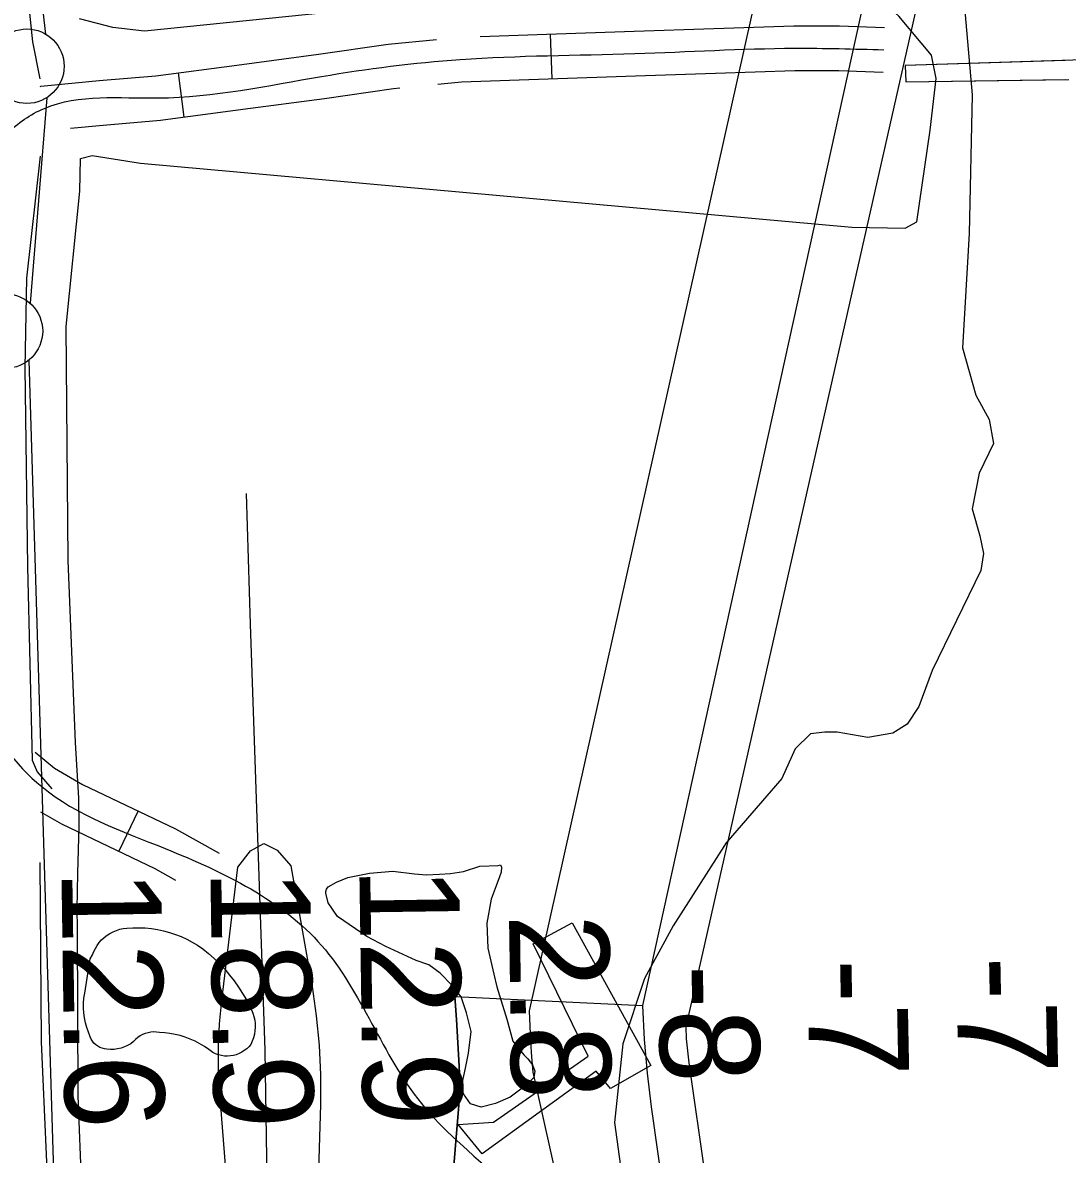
# Model space of a CAD drawing. Extents: x 3651524 to 3689615, y 505651 to 531377.
# Drawn here: x 3657251 to 3657953, y 524242 to 525001 of the extents above; entities that cross this region are included whole.
import ezdxf

# ---------------------------------------------------------------- set-up
doc = ezdxf.new("R2010")
doc.units = 0
for name, color, linetype in [('V-CHAN-DOCK', 7, 'Continuous'), ('V-FLOD-BASE', 7, 'Continuous'), ('V-LEVE-TOET', 7, 'Continuous'), ('V-RIVR-EDGE', 7, 'Continuous'), ('V-RIVR-RANG', 7, 'Continuous'), ('V-ROAD-CNTR', 7, 'Continuous'), ('V-SITE-VEGE', 7, 'Continuous'), ('V-SURV-LINE', 7, 'Continuous'), ('V-TOPO-DPTH', 7, 'Continuous'), ('V-TOPO-MINR', 7, 'Continuous'), ('V-TOPO-SHOR', 7, 'Continuous'), ('V-TOPO-WATR', 7, 'Continuous'), ('V-UTIL-LINE', 7, 'Continuous')]:
    doc.layers.add(name, color=color, linetype=linetype)

msp = doc.modelspace()

# ---------------------------------------------------------------- linework, layer by layer
at = {"layer": 'V-CHAN-DOCK'}
for points in [[(3657963.161, 524976.383), (3657843.67, 524972.508), (3657844.08, 524961.707), (3657953.55, 524963.231)], [(3657951.172, 524975.996), (3657843.67, 524972.508), (3657844.08, 524961.707), (3657951.551, 524963.202)], [(3657543.487, 524261.701), (3657567.221, 524263.255), (3657630.83, 524307.57), (3657593.833, 524382.901), (3657620.162, 524397.055), (3657672.994, 524301.295), (3657645.856, 524285.969), (3657636.183, 524297.598), (3657559.736, 524242.052), (3657543.487, 524261.701)]]:
    msp.add_lwpolyline(points, dxfattribs=at)
at = {"layer": 'V-FLOD-BASE'}
for points in [[(3657233.676, 525796.15), (3657236.817, 525673.28), (3657238.124, 525513.246), (3657239.543, 525359.705), (3657243.953, 525174.816), (3657248.712, 525076.717), (3657257.785, 524988.581), (3657262.659, 524963.696)], [(3657262.921, 524911.732), (3657253.797, 524829.82), (3657252.732, 524769.613), (3657254.508, 524636.141), (3657257.527, 524506.189), (3657260.932, 524498.451), (3657270.767, 524487.058)], [(3657262.808, 524437.601), (3657263.632, 524317.136), (3657270.407, 524165.86), (3657277.304, 524021.671), (3657283.95, 523829.657), (3657284.927, 523784.764)]]:
    msp.add_lwpolyline(points, dxfattribs=at)
at = {"layer": 'V-LEVE-TOET'}
for points in [[(3657290.039, 524910.063), (3657297.915, 524912.164), (3657330.308, 524907.109), (3657807.806, 524863.952), (3657843.636, 524863.317), (3657851.551, 524867.659), (3657860.478, 524929.103), (3657864.451, 524963.755), (3657861.369, 524979.49), (3657839.429, 525005.639), (3657819.592, 525023.909), (3657797.318, 525031.024), (3657765.986, 525032.697), (3657511.399, 525013.675), (3657332.989, 524995.546), (3657311.756, 524998.161), (3657289.334, 525003.955)], [(3657293.346, 524155.741), (3657288.474, 524281.003), (3657288.095, 524393.194), (3657287.735, 524406.191), (3657288.163, 524430.392), (3657289.203, 524461.925), (3657288.947, 524480.824), (3657286.653, 524518.063), (3657281.73, 524640.374), (3657280.372, 524797.457), (3657289.652, 524888.223), (3657290.039, 524910.063)]]:
    msp.add_lwpolyline(points, dxfattribs=at)
at = {"layer": 'V-RIVR-EDGE'}
msp.add_lwpolyline([(3657882.775, 525019.576), (3657888.613, 524952.926), (3657886.582, 524859.88), (3657882.19, 524783.049), (3657891.116, 524751.21), (3657900.081, 524734.979), (3657903.043, 524718.763), (3657893.388, 524698.976), (3657888.526, 524674.975), (3657893.885, 524656.952), (3657896.256, 524644.939), (3657894.427, 524633.537), (3657861.844, 524566.381), (3657852.779, 524542.391), (3657844.945, 524530.404), (3657835.325, 524524.424), (3657818.509, 524521.464), (3657798.107, 524525.116), (3657789.702, 524525.137), (3657780.094, 524523.96), (3657769.863, 524513.78), (3657760.81, 524493.992), (3657723.483, 524450.861), (3657687.926, 524395.118), (3657668.628, 524359.746), (3657654.112, 524315.959), (3657648.578, 524263.143), (3657653.296, 524228.913)], dxfattribs=at)
at = {"layer": 'V-ROAD-CNTR'}
for p, q in [((3657605.412, 524993.672), (3657606.42, 524963.689)), ((3657355.52, 524967.698), (3657359.448, 524937.956)), ((3657328.645, 524472.239), (3657315.762, 524445.146))]:
    msp.add_line(p, q, dxfattribs=at)
for points in [[(3657558.405, 524992.091), (3657603.049, 524993.593), (3657661.682, 524995.563), (3657715.211, 524997.363), (3657768.992, 524999.17), (3657799.559, 524999.21), (3657829.888, 524998.15)], [(3657263.03, 524958.59), (3657263.319, 524958.657), (3657302.595, 524962.439), (3657340.502, 524965.714), (3657395.041, 524972.917), (3657449.814, 524980.093), (3657496.482, 524986.927), (3657528.948, 524990.128)], [(3657530.022, 524960.088), (3657545.902, 524961.654), (3657604.041, 524963.609), (3657662.672, 524965.579), (3657716.221, 524967.379), (3657769.516, 524969.17), (3657799.055, 524969.21), (3657828.84, 524968.168)], [(3657283.312, 524930.443), (3657305.323, 524932.563), (3657343.758, 524935.884), (3657398.953, 524943.173), (3657453.936, 524950.377), (3657500.13, 524957.141), (3657504.385, 524957.561)], [(3657259.698, 524511.607), (3657272.602, 524500.844), (3657291.286, 524490.003), (3657353.843, 524460.257), (3657383.068, 524443.835)], [(3657263.216, 524471.605), (3657277.294, 524463.437), (3657340.037, 524433.603), (3657353.891, 524425.818)]]:
    msp.add_lwpolyline(points, dxfattribs=at)
for points in [[(3657130.748, 524795.433), (3657165.711, 524812.868), (3657188.341, 524836.501), (3657213.423, 524885.57), (3657240.424, 524926.712), (3657265.753, 524943.822), (3657342.13, 524950.799), (3657451.875, 524965.235), (3657544.913, 524976.629), (3657662.177, 524980.571), (3657769.254, 524984.17), (3657829.364, 524983.159)], [(3657129.943, 524655.414), (3657166.389, 524653.332), (3657185.57, 524640.198), (3657200.233, 524605.692), (3657221.299, 524544.671), (3657263.972, 524488.509), (3657346.94, 524446.93), (3657451.918, 524381.84), (3657518.866, 524275.788), (3657590.106, 524205.982), (3657650.646, 524044.599), (3657661.145, 523937.202), (3657682.089, 523855.232), (3657701.882, 523782.87)]]:
    msp.add_spline(points, degree=3, dxfattribs=at)
at = {"layer": 'V-SITE-VEGE'}
msp.add_lwpolyline([(3657570.418, 524435.482), (3657572.044, 524435.992), (3657572.554, 524434.363), (3657572.499, 524431.13), (3657571.362, 524427.914), (3657569.101, 524422.022), (3657565.706, 524412.915), (3657562.724, 524396.789), (3657563.506, 524380.057), (3657567.514, 524362.728), (3657569.519, 524354.063), (3657576.146, 524332.375), (3657580.201, 524317.742), (3657587.586, 524308.444), (3657590.234, 524305.702), (3657593.403, 524301.87), (3657594.945, 524297.528), (3657594.328, 524293.223), (3657588.293, 524287.401), (3657578.456, 524280.024), (3657568.675, 524275.883), (3657558.925, 524273.36), (3657551.953, 524275.639), (3657547.216, 524282.195), (3657546.26, 524289.222), (3657548.599, 524299.429), (3657550.399, 524309.64), (3657552.273, 524324.169), (3657549.256, 524336.627), (3657545.672, 524347.475), (3657539.338, 524355.136), (3657531.393, 524363.367), (3657523.941, 524368.891), (3657515.364, 524371.74), (3657495.037, 524381.267), (3657482.215, 524387.966), (3657474.75, 524392.951), (3657462.497, 524401.255), (3657456.189, 524410.535), (3657454.686, 524417.033), (3657454.704, 524418.11), (3657455.271, 524419.718), (3657456.377, 524421.318), (3657461.827, 524424.457), (3657469.431, 524427.558), (3657484.046, 524430.536), (3657499.709, 524431.877), (3657514.235, 524430.001), (3657522.313, 524429.319), (3657530.949, 524429.706), (3657538.504, 524430.112), (3657547.159, 524431.576), (3657558.011, 524435.16)], close=True, dxfattribs=at)
at = {"layer": 'V-SURV-LINE'}
for points in [[(3657253.9, 525101.842), (3657266.601, 524993.701)], [(3657267.374, 524950.976), (3657256.193, 524812.97)], [(3657255.23, 524774.761), (3657272.705, 524200.332)]]:
    msp.add_lwpolyline(points, dxfattribs=at)
for centre in [(3657254.036, 524972.092), (3657239.629, 524794.272)]:
    msp.add_circle(centre, 25, dxfattribs=at)
at = {"layer": 'V-TOPO-DPTH'}
for points in [[(3657928.431, 525527.204), (3657667.418, 524341.541), (3657668.44, 524318.793), (3657670.473, 524296.113), (3657673.18, 524273.478), (3657701.204, 524076.431), (3657708.034, 524033.365), (3657724.891, 523947.862), (3657734.917, 523905.425), (3657745.627, 523863.123), (3657756.334, 523820.821), (3657858.399, 523191.384), (3657860.754, 523167.794), (3657862.805, 523144.18), (3657864.401, 523120.531), (3657865.694, 523096.859), (3657876.251, 522862.033)], [(3657505.952, 522908.63), (3657475.119, 523077.48), (3657471.403, 523102.363), (3657468.768, 523127.324), (3657467.752, 523152.404), (3657467.815, 523177.563), (3657478.27, 523476.767), (3657480.493, 523507.936), (3657544.86, 524285.367), (3657544.174, 524300.963), (3657543.38, 524316.552), (3657542.425, 524332.132), (3657541.363, 524347.706), (3657667.418, 524341.541)], [(3657667.418, 524341.541), (3657668.44, 524318.793), (3657670.473, 524296.113), (3657673.18, 524273.478), (3657701.204, 524076.431), (3657708.034, 524033.365), (3657724.891, 523947.862), (3657734.917, 523905.425), (3657745.627, 523863.123), (3657756.334, 523820.821), (3657858.399, 523191.384), (3657860.754, 523167.794), (3657862.805, 523144.18), (3657864.401, 523120.531), (3657865.694, 523096.859), (3657876.251, 522862.033)]]:
    msp.add_lwpolyline(points, dxfattribs=at)
at = {"layer": 'V-TOPO-MINR'}
for points in [[(3657857.317, 525529.096), (3657591.228, 524337.927), (3657591.643, 524327.668), (3657592.181, 524317.416), (3657592.904, 524307.175), (3657593.75, 524296.942), (3657693.98, 523847.622)], [(3657967.261, 525524.579), (3657696.365, 524327.331), (3657696.729, 524319.222), (3657697.454, 524311.137), (3657698.418, 524303.068), (3657709.305, 524226.518), (3657711.317, 524214.326), (3657713.687, 524202.213), (3657716.594, 524190.218), (3657719.859, 524178.3), (3657723.439, 524166.456), (3657727.077, 524154.63), (3657730.803, 524142.832), (3657734.589, 524131.052), (3657886.396, 523224.776), (3657890.414, 523185.526), (3657894.063, 523146.244), (3657897.155, 523106.914), (3657899.876, 523067.552), (3657960.654, 522087.831)], [(3657382.603, 524313.75), (3657383.394, 524329.363), (3657384.809, 524344.963), (3657395.625, 524434.386), (3657404.242, 524445.38), (3657413.023, 524450.228), (3657422.051, 524445.857), (3657431.244, 524435.342), (3657445.478, 524354.362), (3657448.323, 524334.639), (3657450.355, 524314.857), (3657451.169, 524294.987), (3657451.171, 524275.06), (3657443.322, 524019.237)], [(3657541.363, 524347.706), (3657542.425, 524332.132), (3657543.38, 524316.552), (3657544.174, 524300.963), (3657544.86, 524285.367), (3657480.493, 523507.936), (3657478.27, 523476.767), (3657467.815, 523177.563), (3657467.752, 523152.404), (3657468.768, 523127.324), (3657471.403, 523102.363), (3657475.119, 523077.48), (3657505.952, 522908.63)], [(3657410.572, 523939.893), (3657383.511, 524282.473), (3657382.745, 524298.118), (3657382.603, 524313.75)]]:
    msp.add_lwpolyline(points, dxfattribs=at)
at = {"layer": 'V-TOPO-SHOR'}
for points in [[(3657298.098, 524375.582), (3657298.945, 524377.8), (3657299.99, 524379.932), (3657301.225, 524381.961), (3657302.636, 524383.872), (3657304.215, 524385.646), (3657305.945, 524387.272), (3657307.819, 524388.734), (3657309.814, 524390.018), (3657311.919, 524391.12), (3657314.115, 524392.025), (3657316.382, 524392.73), (3657318.707, 524393.227), (3657321.064, 524393.512), (3657325.207, 524393.784), (3657329.358, 524393.829), (3657333.507, 524393.645), (3657337.638, 524393.233), (3657341.74, 524392.594), (3657345.802, 524391.728), (3657349.81, 524390.641), (3657353.75, 524389.334), (3657357.612, 524387.81), (3657361.385, 524386.078), (3657365.057, 524384.138), (3657368.616, 524381.998), (3657372.051, 524379.667), (3657375.977, 524376.483), (3657379.753, 524373.12), (3657383.372, 524369.591), (3657386.827, 524365.901), (3657390.11, 524362.055), (3657393.215, 524358.065), (3657396.133, 524353.938), (3657398.861, 524349.681), (3657401.393, 524345.304), (3657403.721, 524340.819), (3657404.841, 524338.689), (3657405.763, 524336.465), (3657406.476, 524334.167), (3657406.973, 524331.814), (3657407.254, 524329.424), (3657407.313, 524327.017), (3657407.151, 524324.617), (3657406.771, 524322.242), (3657406.175, 524319.911), (3657405.366, 524317.644), (3657404.352, 524315.461), (3657403.039, 524313.925), (3657401.583, 524312.528), (3657399.99, 524311.283), (3657398.282, 524310.203), (3657396.475, 524309.3), (3657394.587, 524308.583), (3657392.635, 524308.059), (3657390.641, 524307.733), (3657388.623, 524307.609), (3657386.606, 524307.686), (3657384.605, 524307.967), (3657382.641, 524308.446), (3657380.736, 524309.12), (3657378.91, 524309.978), (3657376.096, 524312.143), (3657373.159, 524314.138), (3657370.111, 524315.956), (3657366.962, 524317.593), (3657363.722, 524319.04), (3657360.402, 524320.298), (3657357.012, 524321.357), (3657353.568, 524322.215), (3657350.08, 524322.868), (3657346.557, 524323.317), (3657343.016, 524323.556), (3657341.106, 524323.798), (3657339.178, 524323.841), (3657337.257, 524323.683), (3657335.363, 524323.329), (3657333.516, 524322.778), (3657331.736, 524322.041), (3657330.04, 524321.121), (3657328.451, 524320.034), (3657326.983, 524318.784), (3657325.651, 524317.392), (3657323.732, 524315.964), (3657321.676, 524314.746), (3657319.503, 524313.744), (3657317.24, 524312.974), (3657314.912, 524312.442), (3657312.538, 524312.151), (3657310.148, 524312.108), (3657307.764, 524312.315), (3657306.13, 524312.477), (3657304.53, 524312.856)], [(3657304.53, 524312.856), (3657302.996, 524313.447), (3657301.555, 524314.242), (3657300.236, 524315.221), (3657299.058, 524316.368), (3657298.044, 524317.662), (3657297.217, 524319.083), (3657296.586, 524320.601), (3657295.286, 524323.659), (3657294.198, 524326.798), (3657293.33, 524330.005), (3657292.683, 524333.266), (3657292.263, 524336.561), (3657292.07, 524339.879), (3657292.107, 524343.201), (3657292.371, 524346.512), (3657292.865, 524349.797), (3657296.433, 524372.913), (3657298.098, 524375.582)]]:
    msp.add_lwpolyline(points, dxfattribs=at)
at = {"layer": 'V-TOPO-WATR'}
msp.add_lwpolyline([(3657928.431, 525527.204), (3657667.418, 524341.541), (3657668.44, 524318.793), (3657670.473, 524296.113), (3657673.18, 524273.478), (3657701.204, 524076.431), (3657708.034, 524033.365), (3657724.891, 523947.862), (3657734.917, 523905.425), (3657745.627, 523863.123), (3657756.334, 523820.821), (3657858.399, 523191.384), (3657860.754, 523167.794), (3657862.805, 523144.18), (3657864.401, 523120.531), (3657865.694, 523096.859), (3657876.251, 522862.033)], dxfattribs=at)
at = {"layer": 'V-UTIL-LINE'}
msp.add_lwpolyline([(3657401.21, 524685.192), (3657403.834, 524597.476), (3657408.577, 524460.819), (3657413.693, 524311.631), (3657415.137, 524224.531), (3657419.034, 524107.568), (3657418.792, 524026.463)], dxfattribs=at)

# ---------------------------------------------------------------- texts
at = {"layer": 'V-RIVR-RANG'}
for s, rotation, p in [('12.6', 270.838326, (3657277.195, 524432.649)), ('18.9', 270.838326, (3657377.203, 524432.78)), ('12.9', 270.838326, (3657477.189, 524434.493)), ('2.8', 270.838326, (3657577.664, 524402.71)), ('-8', 270.838326, (3657678.17, 524368.817)), ('-7', 271.123444, (3657777.87, 524372.47)), ('-7', 271.123444, (3657877.855, 524374.183))]:
    msp.add_text(s, height=67, rotation=rotation, dxfattribs=at).set_placement(p)

doc.saveas('drawing.dxf')
